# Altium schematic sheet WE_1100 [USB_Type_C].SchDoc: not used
size A3; Date: not used; Author: not used; CompanyName: Würth Elektronik eiSos GmbH & Co. KG; Engineer: not used; Organization: not used; Address1: Max-Eyth-Str. 1; Address2: 74638 Waldenburg; Address3: not used; Address4: Germany; DocumentNumber: not used; Revision: not used; PageSetup: Record=PageOptions¦CenterHorizontal=True¦CenterVertical=True¦PrintScale=0.97¦XCorrection=1.00¦YCorrection=1.00¦PrintKind=0¦BorderSize=5000000¦LeftOffset=0¦BottomOffset=0¦Orientation=1¦PaperLength=1000¦PaperWidth=1000¦Scale=100¦PaperSource=7¦PrintQuality=600¦MediaType=1¦DitherType=10¦PaperKind=A4¦PrintScaleMode=1
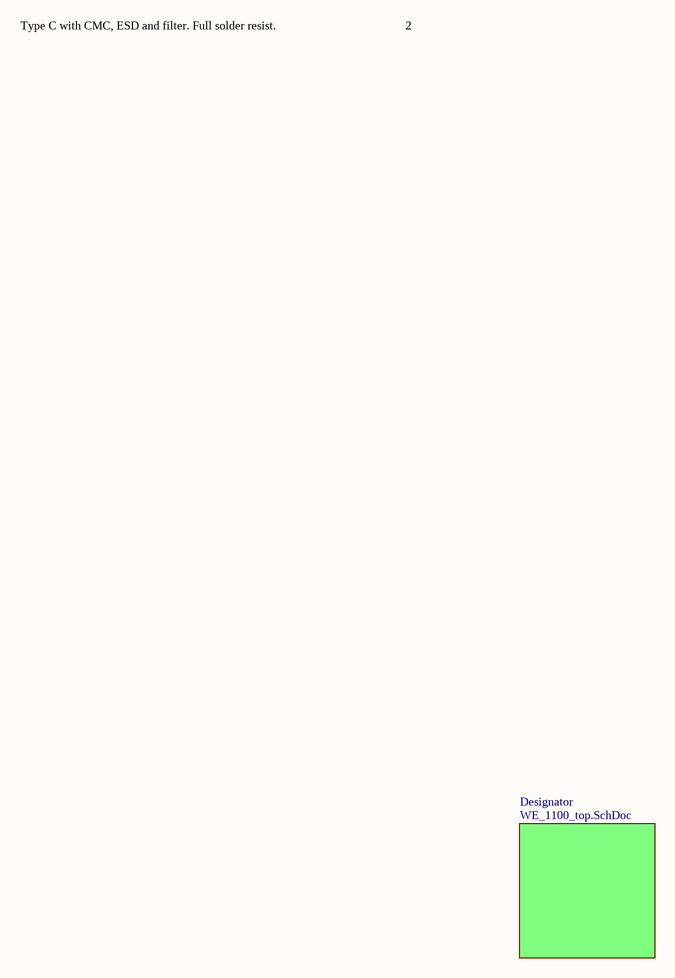
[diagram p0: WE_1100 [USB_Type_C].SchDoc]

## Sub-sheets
Designator = WE_1100_top.SchDoc: no entries

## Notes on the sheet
- Type C with CMC, ESD and filter. Full solder resist.
- 2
